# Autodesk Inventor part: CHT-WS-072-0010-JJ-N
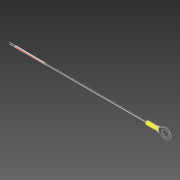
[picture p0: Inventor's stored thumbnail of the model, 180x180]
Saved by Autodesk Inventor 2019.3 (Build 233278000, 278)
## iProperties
Created: 2017-05
Part Number: CHT-WS-072-0010-JJ-N
Material: Generic
Document SubType Name: Modeling
Designer: JN
Density: 1 g/cm^3
Appearance: Steel - Polished
Author: JN
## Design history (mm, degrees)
sketch "Sketch1"
  geometry: L1 (-3.534, 6.574)-(-10.033, 3.097); L2 (-10.033, 3.097)-(-10.033, -3.161); L3 (-10.033, -3.161)-(-3.425, -6.697); L4 (-10.033, -0.032)-(7.494, -0.032); L5 (0.001, 7.461)-(0.001, -7.525); C1 r 5.258 at (0.001, -0.032); A1 r 7.493 centre (0.001, -0.032) between (-3.534, -6.639) and (-3.534, 6.574)
  constraints: 10 end point, 5 point on circle, 2 centre point, 2 tangent, 2 vertical, 1 coincident, 1 midpoint, 1 point on line, 1 other
  dimensions: "d0" = 10.5156 diameter of C1; "d1" = 14.986 diameter of A1
extrude "Extrusion1" new body sketch "Sketch1" stored distance "d7" = 1.0668; taper "d8" = 0 deg
sketch "Sketch3"
  geometry: L1 (-1.067, 0)-(0, 0) reference; L2 (0, 6.258)-(0, 0) reference; L3 (-1.067, 6.258)-(0, 6.258) reference; L4 (-1.067, 0)-(-1.067, 6.258) reference; L5 (0.317, 6.575)-(-1.702, 6.575); L6 (-1.702, 6.575)-(-1.702, -0.318); L7 (-1.702, -0.318)-(0.317, -0.318); L8 (0.317, -0.318)-(0.317, 6.575); L9 (-0.692, 6.575)-(-0.692, -0.318); L10 (0.318, 3.129)-(-1.702, 3.129); 1 further point
  constraints: 12 end point, 6 parallel, 5 midpoint, 1 horizontal, 1 perpendicular
  dimensions: "d15" = 0.3175 distance between parallel lines of L2 L8; "d16" = 0.635 distance between parallel lines of L4 L6; "d17" = 0.3175 distance between parallel lines of L3 L5; "d18" = 0.3175 distance between parallel lines of L1 L7
  node "Projected Loop1"
workplane "Work Plane1"
sketch "Sketch4"
  geometry: L1 (0.317, -0.318)-(0.317, 6.575) reference; L2 (0.317, 6.575)-(-1.702, 6.575) reference; L3 (-1.702, 6.575)-(-1.702, -0.318) reference; L4 (-1.702, -0.318)-(0.317, -0.318) reference; L5 (0.317, 3.129)-(-1.702, 3.129); L6 (-0.692, 6.575)-(-0.692, -0.318); L7 (-2.337, 5.064)-(-2.337, 1.193); A1 r 2.54 centre (-0.692, 3.129) between (-2.337, 1.193) and (-2.337, 5.064); 2 further points
  constraints: 6 end point, 5 midpoint, 2 point on circle, 1 centre point, 1 coincident, 1 point on line, 1 vertical
  dimensions: "d37" = 5.08 diameter of A1; "d38" = 0.635 distance between parallel lines of L3 L7
sketch "3D Sketch1"
loft "Loft1" sketch "Sketch4", "3D Sketch1" dims "d21" = 0, "d22" = 90 deg, "d25" = 0, "d26" = 90 deg, "d39" = 0, "d40" = 90 deg
sketch "Sketch5"
  geometry: L1 (-0.635, 5.382)-(-0.635, 1.511) reference; A1 r 2.54 centre (1.01, 3.446) between (1.221, 0.915) and (1.928, 5.814) reference; A2 r 2.54 centre (1.01, 3.446) between (1.928, 5.814) and (-0.635, 5.382) reference; A3 r 2.54 centre (1.01, 3.446) between (1.928, 5.814) and (-0.635, 5.382) reference; A4 r 2.54 centre (1.01, 3.446) between (-0.635, 1.511) and (1.221, 0.915) reference; A5 r 2.54 centre (1.01, 3.446) between (1.221, 0.915) and (1.928, 5.814) reference
extrude "Extrusion3" new body sketch "Sketch5" distance "d27" = 12.7; taper "d28" = 0 deg
sketch "Sketch6" dims "d29" = 1.27, "d30" = 1.778
  geometry: L1 (2.019, 0)-(2.019, 6.893) reference; L2 (0, 6.893)-(0, 0) reference; L3 (2.019, 6.893)-(0, 6.893) reference; L4 (0, 0)-(2.019, 0) reference; L5 (2.019, 0)-(2.019, 6.893) reference; L6 (2.019, 6.893)-(0, 6.893) reference; L7 (1.01, 6.893)-(1.01, 0); L8 (0, 0)-(2.019, 0) reference; L9 (0, 6.893)-(0, 0) reference; L10 (0, 3.446)-(2.019, 3.446); 2 further points; 1 other entity
  constraints: 5 midpoint, 4 end point, 2 other
  node "Projected Loop4"
extrude "Extrusion4" cut sketch "Sketch6" stored distance "d32" = 12.7; taper "d33" = 0 deg
extrude "Extrusion5" new body sketch "Sketch6" distance "d34" = 152.4; taper "d35" = 0 deg
sketch "Sketch7"
  geometry: L1 (2.28, 3.446)-(-0.26, 3.446) reference; L2 (1.01, 5.224)-(1.01, 1.668) reference; C1 r 0.635 at (1.01, 4.081); C2 r 0.635 at (1.01, 2.811); 1 further point; 1 other entity
  constraints: 4 end point, 2 centre point, 2 horizontal, 2 vertical, 1 point on line, 1 symmetric about line, 1 tangent, 6 other
  dimensions: "d41" = 1.27 diameter of C1
workplane "Work Plane2"
sketch "Sketch8"
  geometry: C1 r 0.635 at (1.01, 4.081) reference; C2 r 0.635 at (1.01, 2.811) reference; C3 r 0.635 at (1.01, 4.399); C4 r 0.635 at (1.01, 2.494)
  constraints: 2 centre point
  dimensions: "d43" = 1.27 diameter of C3; "d45" = 0.3175 distance of C1.centre C3.centre; "d46" = 1.27 diameter of C4; "d47" = 0.3175 distance of C2.centre C4.centre
sketch "3D Sketch2"
loft "Loft2" dims "d48" = 0, "d49" = 90 deg, "d50" = 0, "d51" = 90 deg, "d52" = 0, "d53" = 90 deg
loft "Loft3" dims "d54" = 0, "d55" = 90 deg, "d56" = 0, "d57" = 90 deg, "d58" = 0, "d59" = 90 deg
sketch "Sketch9"
  geometry: C1 r 0.381 at (0, 0)
  constraints: 1 centre point
  dimensions: "d60" = 0.762 diameter of C1
sketch "Sketch10"
  geometry: C1 r 0.381 at (0, 0)
  constraints: 1 centre point
  dimensions: "d61" = 0.762 diameter of C1
extrude "Extrusion6" join sketch "Sketch9" distance "d62" = 8.46667; taper "d63" = 0 deg
extrude "Extrusion7" join sketch "Sketch10" distance "d64" = 8.46667; taper "d65" = 0 deg
body "Solid1"
body "Solid2"
body "Solid3"
body "Solid4"
node "Projected Loop5"
other parameters: "d3" = 14.986 (derived), "d5" = 10.49782 (derived), "d19" = 5.08, "d42" = 44.45
